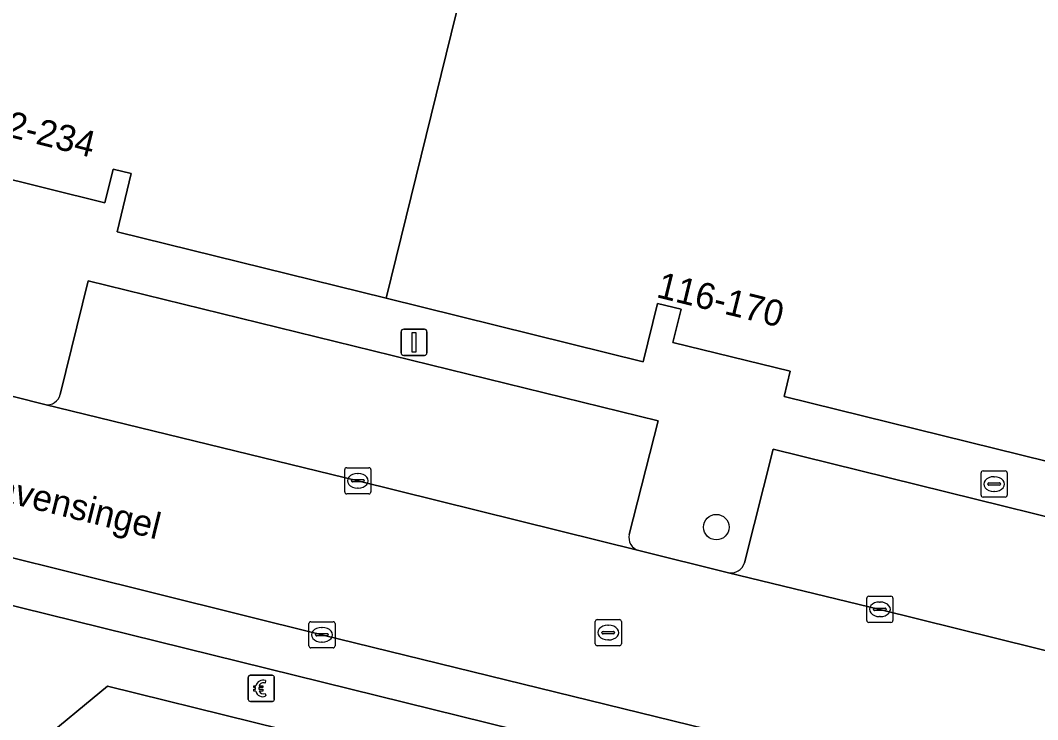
# Model space of a CAD drawing. Extents: x 161771 to 163125, y 382475 to 383179.
# Drawn here: x 162036.28 to 162075.22, y 383052.06 to 383078.82 of the extents above; entities that cross this region are included whole.
import ezdxf

# ---------------------------------------------------------------- set-up
doc = ezdxf.new("R2010")
doc.units = 0
for name, color, linetype in [('IMGEO_Betaalautomaat', 7, 'Continuous'), ('IMGEO_Boom', 7, 'Continuous'), ('IMGEO_Brandkraan', 7, 'Continuous'), ('IMGEO_Groenvoorziening', 7, 'Continuous'), ('IMGEO_Kolk', 7, 'Continuous'), ('IMGEO_Lichtmast', 7, 'Continuous'), ('IMGEO_Openbare_ruimte_label', 7, 'Continuous'), ('IMGEO_Pand', 7, 'Continuous'), ('IMGEO_Pand_nummerreeks', 7, 'Continuous'), ('IMGEO_Parkeervlak_open', 7, 'Continuous'), ('IMGEO_Rijbaan_lokaal_open', 7, 'Continuous'), ('IMGEO_Rioolput', 7, 'Continuous'), ('IMGEO_Voetpad_open', 7, 'Continuous')]:
    doc.layers.add(name, color=color, linetype=linetype)

msp = doc.modelspace()

# ---------------------------------------------------------------- linework, layer by layer
at = {"layer": 'IMGEO_Betaalautomaat'}
for p, q in [((162045.003, 383052.836), (162045.003, 383053.677)), ((162045.003, 383053.677), (162045.003, 383052.836)), ((162045.078, 383053.76), (162045.919, 383053.76)), ((162045.919, 383053.76), (162045.078, 383053.76)), ((162045.665, 383053.565), (162045.648, 383053.465)), ((162046.002, 383053.686), (162046.002, 383052.845)), ((162046.002, 383052.845), (162046.002, 383053.686)), ((162045.286, 383053.224), (162045.286, 383053.292)), ((162045.407, 383053.292), (162045.407, 383053.224)), ((162045.652, 383053.059), (162045.674, 383052.972)), ((162045.928, 383052.761), (162045.087, 383052.761)), ((162045.087, 383052.761), (162045.928, 383052.761))]:
    msp.add_line(p, q, dxfattribs=at)
for points in [[(162045.286, 383053.292), (162045.217, 383053.292), (162045.217, 383053.361), (162045.296, 383053.361)], [(162045.291, 383053.155), (162045.217, 383053.155), (162045.217, 383053.224), (162045.286, 383053.224)], [(162045.418, 383053.361), (162045.565, 383053.361), (162045.565, 383053.292), (162045.407, 383053.292)], [(162045.407, 383053.224), (162045.565, 383053.224), (162045.565, 383053.155), (162045.421, 383053.155)]]:
    msp.add_lwpolyline(points, dxfattribs=at)
for centre, radius, start, end in [((162045.081, 383053.683), 0.0779, 92.4484, 184.2845), ((162045.081, 383053.683), 0.0779, 92.4484, 184.2845), ((162045.579, 383053.285), 0.293, 73.014, 165.0139), ((162045.925, 383053.683), 0.0779, 2.4484, 94.2845), ((162045.925, 383053.683), 0.0779, 2.4484, 94.2845), ((162045.585, 383053.298), 0.179, 69.3236, 159.5683), ((162045.081, 383052.839), 0.0779, 182.4484, 274.2845), ((162045.081, 383052.839), 0.0779, 182.4484, 274.2845), ((162045.552, 383053.21), 0.267, 191.8096, 297.0389), ((162045.585, 383053.225), 0.179, 202.7625, 291.8693), ((162045.925, 383052.839), 0.0779, 272.4484, 4.2845), ((162045.925, 383052.839), 0.0779, 272.4484, 4.2845)]:
    msp.add_arc(centre, radius, start, end, dxfattribs=at)
at = {"layer": 'IMGEO_Boom'}
msp.add_circle((162062.919, 383059.431), 0.489, dxfattribs=at)
at = {"layer": 'IMGEO_Brandkraan'}
for p, q in [((162073.055, 383060.653), (162073.055, 383061.505)), ((162073.13, 383061.579), (162073.982, 383061.579)), ((162073.543, 383061.359), (162073.568, 383061.359)), ((162074.056, 383061.505), (162074.056, 383060.653)), ((162073.314, 383061.073), (162073.314, 383061.085)), ((162073.752, 383061.036), (162073.354, 383061.036)), ((162073.357, 383061.122), (162073.755, 383061.122)), ((162073.798, 383061.085), (162073.798, 383061.073)), ((162073.982, 383060.579), (162073.13, 383060.579)), ((162073.566, 383060.799), (162073.541, 383060.799))]:
    msp.add_line(p, q, dxfattribs=at)
for points in [[(162073.055, 383060.653), (162073.055, 383061.505)], [(162073.13, 383061.579), (162073.982, 383061.579)], [(162074.056, 383061.505), (162074.056, 383060.653)], [(162073.982, 383060.579), (162073.13, 383060.579)]]:
    msp.add_lwpolyline(points, dxfattribs=at)
for centre, radius, start, end in [((162073.132, 383061.503), 0.0765, 91.552, 178.448), ((162073.132, 383061.503), 0.0765, 91.552, 178.448), ((162073.98, 383061.503), 0.0765, 1.552, 88.448), ((162073.98, 383061.503), 0.0765, 1.552, 88.448), ((162073.354, 383061.082), 0.0403, 85.8775, 175.7526), ((162073.351, 383061.072), 0.0366, 178.938, 274.7102), ((162073.755, 383061.079), 0.043, 264.8664, 352.4533), ((162073.759, 383061.084), 0.0386, 1.7309, 96.639), ((162073.132, 383060.655), 0.0765, 181.552, 268.448), ((162073.132, 383060.655), 0.0765, 181.552, 268.448), ((162073.98, 383060.655), 0.0765, 271.552, 358.448), ((162073.98, 383060.655), 0.0765, 271.552, 358.448)]:
    msp.add_arc(centre, radius, start, end, dxfattribs=at)
for centre, major_axis, ratio, start_param, end_param in [((162073.542, 383061.079), (-0.387, 0.002), 0.722429, 4.712389, 7.853982), ((162073.567, 383061.079), (-0.39, 0.002), 0.717154, 1.570796, 4.712389)]:
    msp.add_ellipse(centre, major_axis=major_axis, ratio=ratio, start_param=start_param, end_param=end_param, dxfattribs=at)
at = {"layer": 'IMGEO_Groenvoorziening'}
msp.add_lwpolyline([(162039.621, 383053.347), (162036.895, 383051.094), (162037.849, 383049.937), (162039.994, 383051.71), (162050.415, 383049.135), (162050.765, 383050.594)], close=True, dxfattribs=at)
at = {"layer": 'IMGEO_Kolk'}
for p, q in [((162048.697, 383060.779), (162048.697, 383061.631)), ((162048.772, 383061.705), (162049.624, 383061.705)), ((162049.185, 383061.485), (162049.21, 383061.485)), ((162049.698, 383061.631), (162049.698, 383060.779)), ((162048.956, 383061.199), (162048.956, 383061.211)), ((162049.394, 383061.162), (162048.996, 383061.162)), ((162048.999, 383061.248), (162049.397, 383061.248)), ((162049.44, 383061.211), (162049.44, 383061.199)), ((162049.624, 383060.705), (162048.772, 383060.705)), ((162049.208, 383060.925), (162049.183, 383060.925)), ((162068.68, 383055.859), (162068.68, 383056.711)), ((162068.755, 383056.785), (162069.607, 383056.785)), ((162069.681, 383056.711), (162069.681, 383055.859)), ((162068.939, 383056.279), (162068.939, 383056.291)), ((162068.982, 383056.328), (162069.38, 383056.328)), ((162069.168, 383056.565), (162069.193, 383056.565)), ((162069.423, 383056.291), (162069.423, 383056.279)), ((162069.377, 383056.242), (162068.979, 383056.242)), ((162069.191, 383056.005), (162069.166, 383056.005)), ((162047.325, 383054.886), (162047.325, 383055.738)), ((162047.4, 383055.812), (162048.252, 383055.812)), ((162047.813, 383055.592), (162047.838, 383055.592)), ((162048.326, 383055.738), (162048.326, 383054.886)), ((162069.607, 383055.785), (162068.755, 383055.785)), ((162047.584, 383055.306), (162047.584, 383055.318)), ((162048.022, 383055.269), (162047.624, 383055.269)), ((162047.627, 383055.355), (162048.025, 383055.355)), ((162048.068, 383055.318), (162048.068, 383055.306)), ((162048.252, 383054.812), (162047.4, 383054.812)), ((162047.836, 383055.032), (162047.811, 383055.032))]:
    msp.add_line(p, q, dxfattribs=at)
for points in [[(162048.697, 383060.779), (162048.697, 383061.631)], [(162048.772, 383061.705), (162049.624, 383061.705)], [(162049.698, 383061.631), (162049.698, 383060.779)], [(162049.624, 383060.705), (162048.772, 383060.705)], [(162068.68, 383055.859), (162068.68, 383056.711)], [(162068.755, 383056.785), (162069.607, 383056.785)], [(162069.681, 383056.711), (162069.681, 383055.859)], [(162047.325, 383054.886), (162047.325, 383055.738)], [(162047.4, 383055.812), (162048.252, 383055.812)], [(162048.326, 383055.738), (162048.326, 383054.886)], [(162069.607, 383055.785), (162068.755, 383055.785)], [(162048.252, 383054.812), (162047.4, 383054.812)]]:
    msp.add_lwpolyline(points, dxfattribs=at)
for centre, radius, start, end in [((162048.774, 383061.629), 0.0765, 91.552, 178.448), ((162048.774, 383061.629), 0.0765, 91.552, 178.448), ((162049.622, 383061.629), 0.0765, 1.552, 88.448), ((162049.622, 383061.629), 0.0765, 1.552, 88.448), ((162048.996, 383061.208), 0.0403, 85.8775, 175.7526), ((162048.993, 383061.198), 0.0366, 178.938, 274.7102), ((162049.397, 383061.205), 0.043, 264.8664, 352.4533), ((162049.401, 383061.21), 0.0386, 1.7309, 96.639), ((162048.774, 383060.781), 0.0765, 181.552, 268.448), ((162048.774, 383060.781), 0.0765, 181.552, 268.448), ((162049.622, 383060.781), 0.0765, 271.552, 358.448), ((162049.622, 383060.781), 0.0765, 271.552, 358.448), ((162068.757, 383056.709), 0.0765, 91.552, 178.448), ((162068.757, 383056.709), 0.0765, 91.552, 178.448), ((162069.605, 383056.709), 0.0765, 1.552, 88.448), ((162069.605, 383056.709), 0.0765, 1.552, 88.448), ((162068.979, 383056.288), 0.0403, 85.8775, 175.7526), ((162069.384, 383056.29), 0.0386, 1.7309, 96.639), ((162068.976, 383056.278), 0.0366, 178.938, 274.7102), ((162069.38, 383056.285), 0.043, 264.8664, 352.4533), ((162047.402, 383055.736), 0.0765, 91.552, 178.448), ((162047.402, 383055.736), 0.0765, 91.552, 178.448), ((162048.25, 383055.736), 0.0765, 1.552, 88.448), ((162048.25, 383055.736), 0.0765, 1.552, 88.448), ((162068.757, 383055.861), 0.0765, 181.552, 268.448), ((162068.757, 383055.861), 0.0765, 181.552, 268.448), ((162069.605, 383055.861), 0.0765, 271.552, 358.448), ((162069.605, 383055.861), 0.0765, 271.552, 358.448), ((162047.624, 383055.315), 0.0403, 85.8775, 175.7526), ((162047.621, 383055.305), 0.0366, 178.938, 274.7102), ((162048.025, 383055.312), 0.043, 264.8664, 352.4533), ((162048.029, 383055.317), 0.0386, 1.7309, 96.639), ((162047.402, 383054.888), 0.0765, 181.552, 268.448), ((162047.402, 383054.888), 0.0765, 181.552, 268.448), ((162048.25, 383054.888), 0.0765, 271.552, 358.448), ((162048.25, 383054.888), 0.0765, 271.552, 358.448)]:
    msp.add_arc(centre, radius, start, end, dxfattribs=at)
for centre, major_axis, ratio, start_param, end_param in [((162049.184, 383061.205), (-0.387, 0.002), 0.722429, 4.712389, 7.853982), ((162049.209, 383061.205), (-0.39, 0.002), 0.717154, 1.570796, 4.712389), ((162069.167, 383056.285), (-0.387, 0.002), 0.722429, 4.712389, 7.853982), ((162069.192, 383056.285), (-0.39, 0.002), 0.717154, 1.570796, 4.712389), ((162047.812, 383055.312), (-0.387, 0.002), 0.722429, 4.712389, 7.853982), ((162047.837, 383055.312), (-0.39, 0.002), 0.717154, 1.570796, 4.712389)]:
    msp.add_ellipse(centre, major_axis=major_axis, ratio=ratio, start_param=start_param, end_param=end_param, dxfattribs=at)
at = {"layer": 'IMGEO_Lichtmast'}
for p, q in [((162050.855, 383066.104), (162050.855, 383066.904)), ((162050.855, 383066.904), (162050.855, 383066.104)), ((162050.955, 383067.004), (162051.745, 383067.004)), ((162051.745, 383067.004), (162050.955, 383067.004)), ((162051.845, 383066.904), (162051.845, 383066.104)), ((162051.845, 383066.104), (162051.845, 383066.904)), ((162051.745, 383066.004), (162050.955, 383066.004)), ((162050.955, 383066.004), (162051.745, 383066.004))]:
    msp.add_line(p, q, dxfattribs=at)
msp.add_lwpolyline([(162051.275, 383066.879), (162051.425, 383066.879), (162051.425, 383066.129), (162051.275, 383066.129), (162051.275, 383066.879)], dxfattribs=at)
for centre, start, end in [((162050.955, 383066.904), 90, 180), ((162050.955, 383066.904), 90, 180), ((162051.745, 383066.904), 0, 90), ((162051.745, 383066.904), 360, 90), ((162050.955, 383066.104), 180, 270), ((162050.955, 383066.104), 180, 270), ((162051.745, 383066.104), 270, 0), ((162051.745, 383066.104), 270, 0)]:
    msp.add_arc(centre, 0.1, start, end, dxfattribs=at)
at = {"layer": 'IMGEO_Pand'}
msp.add_lwpolyline([(162055.457, 383089.209), (162044.945, 383091.795), (162034.211, 383094.433), (162023.933, 383096.958), (162013.229, 383099.592), (162002.554, 383102.219), (162002.398, 383101.588), (162000.943, 383095.694), (162000, 383091.873), (161998.671, 383086.49), (162000, 383086.162), (162007.929, 383084.205), (162008.083, 383084.167), (162011.001, 383083.447), (162009.707, 383078.205), (162034.801, 383072.012), (162035.033, 383072.954), (162039.519, 383071.847), (162039.835, 383073.131), (162040.519, 383072.961), (162039.99, 383070.731), (162050.287, 383068.19)], close=True, dxfattribs=at)
msp.add_lwpolyline([(162101.897, 383073.061), (162102.95, 383077.249), (162103.009, 383077.483), (162097.561, 383078.833), (162086.853, 383081.477), (162076.61, 383084.007), (162065.874, 383086.647), (162055.457, 383089.209), (162050.287, 383068.19), (162060.124, 383065.762), (162060.674, 383067.992), (162061.569, 383067.774), (162061.255, 383066.501), (162065.749, 383065.393), (162065.519, 383064.431), (162090.746, 383058.205), (162092.04, 383063.448), (162095.667, 383062.618), (162095.777, 383062.593), (162096.874, 383064.159), (162099.641, 383068.107)], dxfattribs=at)
at = {"layer": 'IMGEO_Parkeervlak_open'}
for points in [[(162059.59, 383059.153), (162060.695, 383063.494), (162038.877, 383068.851), (162037.809, 383064.509)], [(162037.223, 383064.125), (162049.194, 383061.203), (162059.949, 383058.539)], [(162063.384, 383057.688), (162069.177, 383056.283), (162081.179, 383053.313), (162082.664, 383052.933), (162082.783, 383053.402), (162083.892, 383057.765), (162065.098, 383062.413), (162063.995, 383058.065)], [(162072.115, 383049.331), (162069.085, 383050.1), (162067.664, 383050.45), (162047.822, 383055.314), (162025.979, 383060.745), (162021.635, 383061.806)], [(162024.15, 383059.344), (162024.691, 383059.219), (162068.875, 383048.306)]]:
    msp.add_lwpolyline(points, dxfattribs=at)
for centre, radius, start, end in [((162037.316, 383064.622), 0.506, 259.4141, 347.0587), ((162060.079, 383059.027), 0.505, 165.5209, 255.1079), ((162063.485, 383058.208), 0.529, 258.9824, 344.3686)]:
    msp.add_arc(centre, radius, start, end, dxfattribs=at)
at = {"layer": 'IMGEO_Rijbaan_lokaal_open'}
for points in [[(162069.177, 383056.283), (162063.384, 383057.688), (162059.949, 383058.539), (162049.194, 383061.203), (162037.223, 383064.125), (162033.778, 383064.992), (162028.286, 383066.342), (162020.65, 383068.276), (162019.594, 383068.478)], [(162020.433, 383062.078), (162021.635, 383061.806), (162025.979, 383060.745), (162047.822, 383055.314), (162067.664, 383050.45), (162069.085, 383050.1), (162072.115, 383049.331), (162072.343, 383049.273)], [(162081.179, 383053.313), (162069.177, 383056.283)]]:
    msp.add_lwpolyline(points, dxfattribs=at)
at = {"layer": 'IMGEO_Rioolput'}
for p, q in [((162058.36, 383055.894), (162059.212, 383055.894)), ((162058.285, 383054.968), (162058.285, 383055.82)), ((162058.773, 383055.674), (162058.798, 383055.674)), ((162059.286, 383055.82), (162059.286, 383054.968)), ((162058.544, 383055.388), (162058.544, 383055.4)), ((162058.982, 383055.351), (162058.584, 383055.351)), ((162058.587, 383055.437), (162058.985, 383055.437)), ((162059.028, 383055.4), (162059.028, 383055.388)), ((162059.212, 383054.894), (162058.36, 383054.894)), ((162058.796, 383055.114), (162058.771, 383055.114))]:
    msp.add_line(p, q, dxfattribs=at)
for points in [[(162058.36, 383055.894), (162059.212, 383055.894)], [(162058.285, 383054.968), (162058.285, 383055.82)], [(162059.286, 383055.82), (162059.286, 383054.968)], [(162059.212, 383054.894), (162058.36, 383054.894)]]:
    msp.add_lwpolyline(points, dxfattribs=at)
for centre, radius, start, end in [((162058.362, 383055.818), 0.0765, 91.552, 178.448), ((162058.362, 383055.818), 0.0765, 91.552, 178.448), ((162059.21, 383055.818), 0.0765, 1.552, 88.448), ((162059.21, 383055.818), 0.0765, 1.552, 88.448), ((162058.584, 383055.397), 0.0403, 85.8775, 175.7526), ((162058.581, 383055.387), 0.0366, 178.938, 274.7102), ((162058.985, 383055.394), 0.043, 264.8664, 352.4533), ((162058.989, 383055.399), 0.0386, 1.7309, 96.639), ((162058.362, 383054.97), 0.0765, 181.552, 268.448), ((162058.362, 383054.97), 0.0765, 181.552, 268.448), ((162059.21, 383054.97), 0.0765, 271.552, 358.448), ((162059.21, 383054.97), 0.0765, 271.552, 358.448)]:
    msp.add_arc(centre, radius, start, end, dxfattribs=at)
for centre, major_axis, ratio, start_param, end_param in [((162058.772, 383055.394), (-0.387, 0.002), 0.722429, 4.712389, 7.853982), ((162058.797, 383055.394), (-0.39, 0.002), 0.717154, 1.570796, 4.712389)]:
    msp.add_ellipse(centre, major_axis=major_axis, ratio=ratio, start_param=start_param, end_param=end_param, dxfattribs=at)
at = {"layer": 'IMGEO_Voetpad_open'}
for points in [[(162095.667, 383062.618), (162092.04, 383063.448), (162090.746, 383058.205), (162065.519, 383064.431), (162065.749, 383065.393), (162061.255, 383066.501), (162061.569, 383067.774), (162060.674, 383067.992), (162060.124, 383065.762), (162050.287, 383068.19), (162039.99, 383070.731), (162040.519, 383072.961), (162039.835, 383073.131), (162039.519, 383071.847), (162035.033, 383072.954), (162034.801, 383072.012), (162009.707, 383078.205)], [(162037.809, 383064.509), (162038.877, 383068.851), (162060.695, 383063.494), (162059.59, 383059.153)], [(162033.778, 383064.992), (162037.223, 383064.125)], [(162063.995, 383058.065), (162065.098, 383062.413), (162083.892, 383057.765), (162082.783, 383053.402), (162087.755, 383054.668)], [(162068.875, 383048.306), (162024.691, 383059.219)], [(162059.949, 383058.539), (162063.384, 383057.688)], [(162036.895, 383051.094), (162039.621, 383053.347), (162050.765, 383050.594), (162052.221, 383050.234), (162053.416, 383049.939), (162054.873, 383049.583), (162065.416, 383047.007)]]:
    msp.add_lwpolyline(points, dxfattribs=at)
for centre, radius, start, end in [((162037.316, 383064.622), 0.506, 259.4141, 347.0587), ((162060.079, 383059.027), 0.505, 165.5209, 255.1079), ((162063.485, 383058.208), 0.529, 258.9824, 344.3686)]:
    msp.add_arc(centre, radius, start, end, dxfattribs=at)

# ---------------------------------------------------------------- texts
at = {"layer": 'IMGEO_Openbare_ruimte_label'}
msp.add_text('Havensingel', height=1, rotation=346.1722, dxfattribs=at).set_placement((162034.353, 383060.718))
at = {"layer": 'IMGEO_Pand_nummerreeks'}
for s, rotation, p in [('172-234', 345.8537, (162034.236, 383074.766)), ('116-170', 346.2032, (162060.587, 383068.239))]:
    msp.add_text(s, height=1, rotation=rotation, dxfattribs=at).set_placement(p)

doc.saveas('drawing.dxf')
